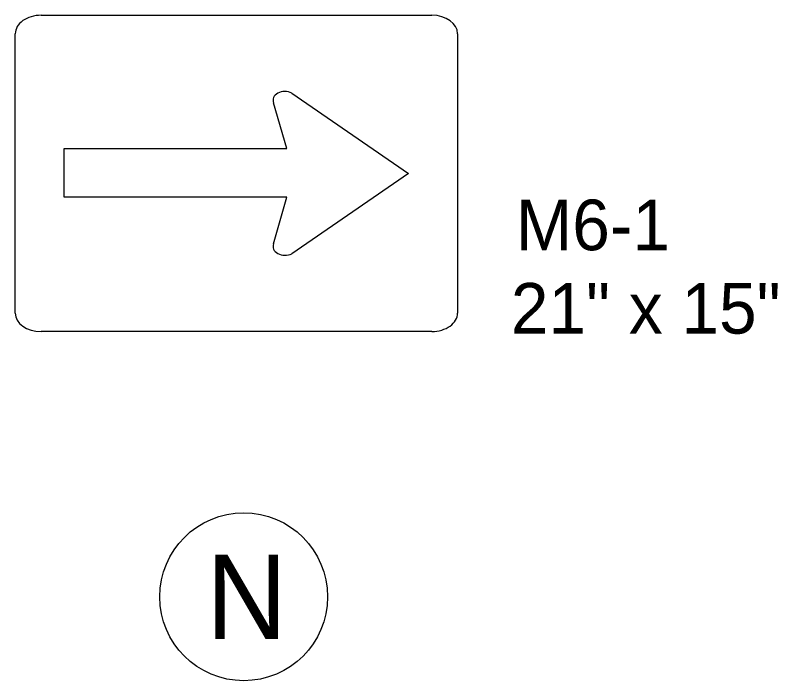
# Model space of a CAD drawing. Extents: x 2157572 to 5059327, y 715220 to 1674494.
# Drawn here: x 2166180.5 to 2166620.6, y 729305.6 to 729689.4 of the extents above; entities that cross this region are included whole.
import ezdxf

# ---------------------------------------------------------------- set-up
doc = ezdxf.new("R2010")
doc.units = 0
for name, color, linetype in [('Exist Cultural Church Label', 7, 'Continuous'), ('Level 56', 7, 'Continuous'), ('Map Preparation County Base Legend Highway Garage or Maintenance Office', 7, 'Continuous')]:
    doc.layers.add(name, color=color, linetype=linetype)

msp = doc.modelspace()

# ---------------------------------------------------------------- linework, layer by layer
at = {"layer": 'Exist Cultural Church Label'}
msp.add_circle((2166312.33, 729354.01), 48.43, dxfattribs=at)
at = {"layer": 'Level 56'}
for p, q in [((2166308.15, 729689.36), (2166308.15, 729689.36)), ((2166340.11, 729644.51), (2166407.39, 729598.17)), ((2166337.19, 729612.46), (2166329.59, 729638.87)), ((2166208.77, 729584.36), (2166208.77, 729612.46)), ((2166208.77, 729612.46), (2166337.19, 729612.46)), ((2166407.39, 729598.17), (2166340.11, 729551.83)), ((2166337.17, 729584.36), (2166208.77, 729584.36)), ((2166329.59, 729557.47), (2166337.17, 729584.36))]:
    msp.add_line(p, q, dxfattribs=at)
for points in [[(2166195.39, 729689.36), (2166420.92, 729689.36)], [(2166180.49, 729517.62), (2166180.49, 729678.72)], [(2166435.81, 729678.72), (2166435.81, 729517.62)], [(2166420.92, 729506.98), (2166195.39, 729506.99)]]:
    msp.add_lwpolyline(points, dxfattribs=at)
for centre, major_axis, ratio, start_param, end_param in [((2166195.38, 729678.72), (-14.89, 0), 0.714286, 4.712162, 6.283185), ((2166420.92, 729678.72), (14.89, 0), 0.714286, 0, 1.570796), ((2166336.19, 729640.39), (6.93, 0), 0.720018, 0.96961, 3.452569), ((2166336.19, 729555.95), (6.93, 0), 0.720018, 2.830617, 5.313577), ((2166195.38, 729517.62), (-14.89, 0), 0.714286, 0, 1.570796), ((2166420.92, 729517.62), (-14.89, 0), 0.714286, 1.570796, 3.141593)]:
    msp.add_ellipse(centre, major_axis=major_axis, ratio=ratio, start_param=start_param, end_param=end_param, dxfattribs=at)
at = {"layer": 'Map Preparation County Base Legend Highway Garage or Maintenance Office'}
msp.add_circle((2166312.33, 729354.01), 48.43, dxfattribs=at)

# ---------------------------------------------------------------- texts
at = {"layer": 'Exist Cultural Church Label'}
msp.add_text('N', height=48.63, dxfattribs=at).set_placement((2166290.57, 729329.69))
at = {"layer": 'Level 56'}
for s, p in [('M6-1', (2166469.48, 729553.86)), ('21" x 15"', (2166466.55, 729505.77))]:
    msp.add_text(s, height=29.18, rotation=360, dxfattribs=at).set_placement(p)

doc.saveas('drawing.dxf')
